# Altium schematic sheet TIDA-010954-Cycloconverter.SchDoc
size 431 x 279 mm; Date: Not shown in title block; ApprovedBy: Not shown in title block; CheckedBy: Not shown in title block; Author: Not shown in title block; CompanyName: Not shown in title block; Engineer: Not shown in title block; Organization: Not shown in title block; Address1: Not shown in title block; Address2: Not shown in title block; Address3: Not shown in title block; Address4: Not shown in title block; DocumentNumber: 2; Revision: Use project parameter SCH_Rev; SheetNumber: 2; SheetTotal: 9; PageSetup: Record=PageOptions¦CenterHorizontal=True¦CenterVertical=True¦PrintScale=1.00¦XCorrection=1.00¦YCorrection=1.00¦PrintKind=0¦BorderSize=5000000¦LeftOffset=0¦BottomOffset=0¦Orientation=2¦PaperLength=1000¦PaperWidth=1000¦Scale=100¦PaperSource=15¦PrintQuality=600¦MediaType=1¦DitherType=10¦PaperKind=Letter¦PrintScaleMode=1
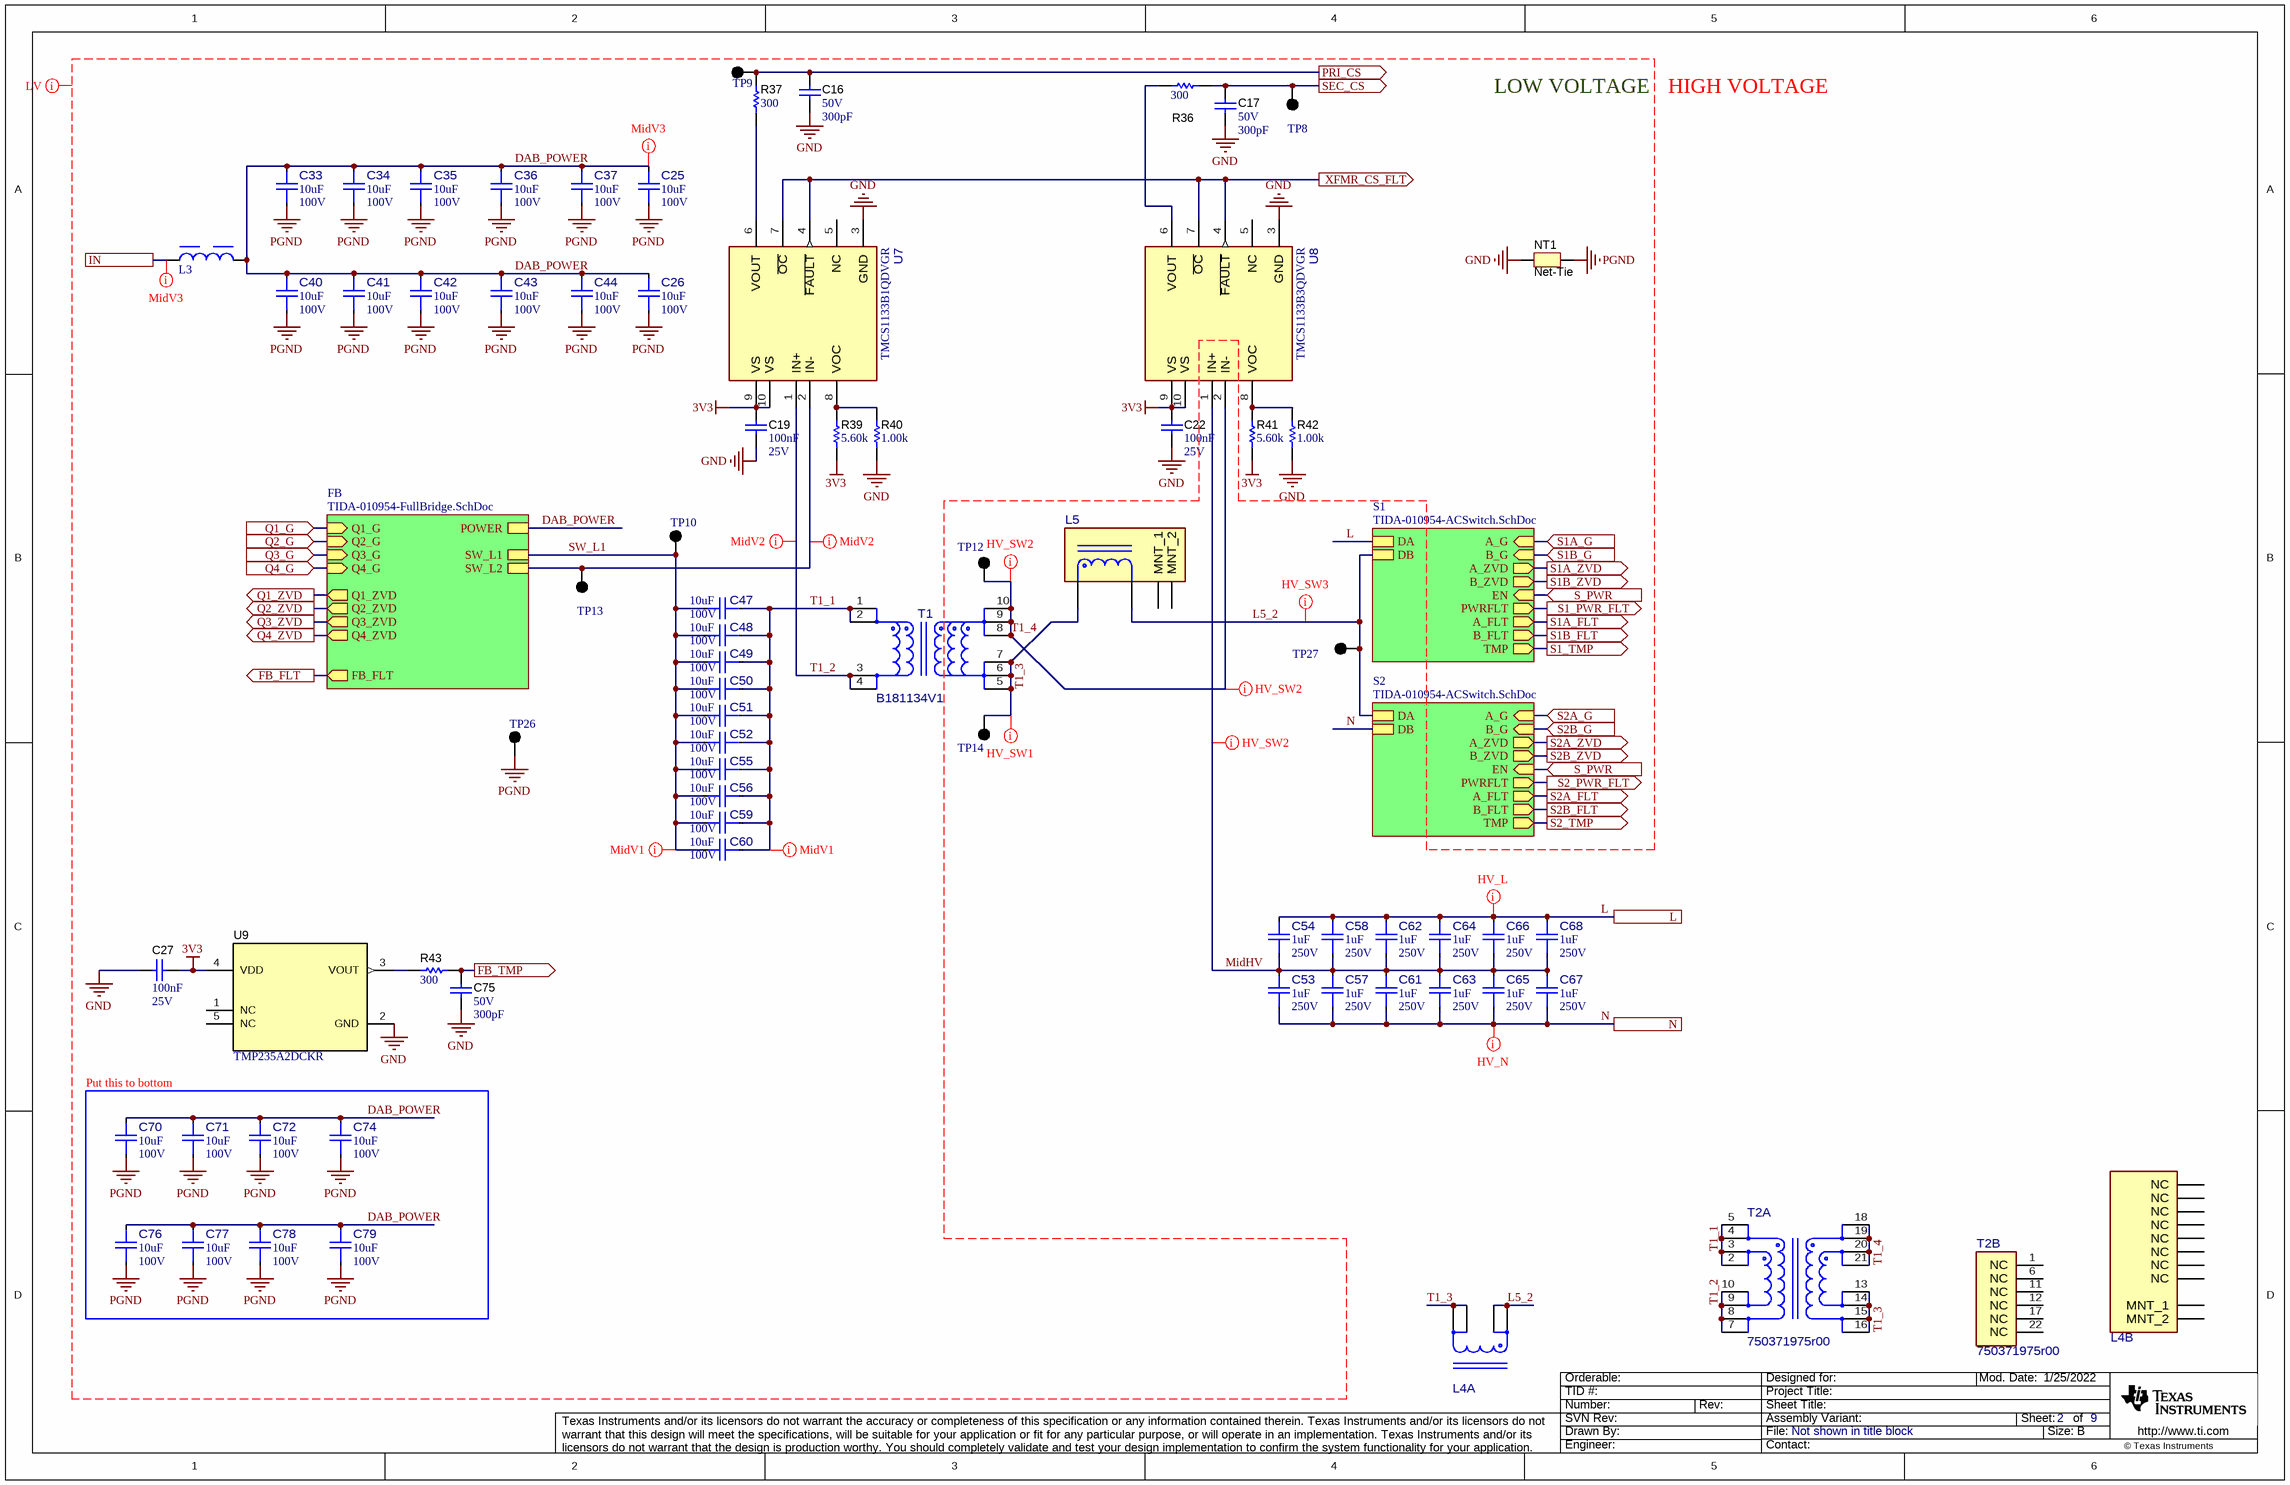
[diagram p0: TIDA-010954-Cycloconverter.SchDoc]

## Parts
C16  VDC_V: 50V  ValueDisplayed: 300pF  [0603]  (hidden comment: GRM1885C1H301JA01D)
C17  VDC_V: 50V  ValueDisplayed: 300pF  [0603]  (hidden comment: GRM1885C1H301JA01D)
C19  Cap_F: 100nF  VDC_V: 25V  [0603]  (hidden comment: CGA3E2X7R1E104K080AA)
C22  Cap_F: 100nF  VDC_V: 25V  [0603]  (hidden comment: CGA3E2X7R1E104K080AA)
C25  ValueDisplayed: 10uF  VDC_V: 100V  [FP-GRM32EC72A106KE05L_1210-MFG]  (hidden comment: GRM32EC72A106KE05L)
C26  ValueDisplayed: 10uF  VDC_V: 100V  [FP-GRM32EC72A106KE05L_1210-MFG]  (hidden comment: GRM32EC72A106KE05L)
C27  Cap_F: 100nF  VDC_V: 25V  [0603]  (hidden comment: CGA3E2X7R1E104K080AA)
C33  ValueDisplayed: 10uF  VDC_V: 100V  [FP-GRM32EC72A106KE05L_1210-MFG]  (hidden comment: GRM32EC72A106KE05L)
C34  ValueDisplayed: 10uF  VDC_V: 100V  [FP-GRM32EC72A106KE05L_1210-MFG]  (hidden comment: GRM32EC72A106KE05L)
C35  ValueDisplayed: 10uF  VDC_V: 100V  [FP-GRM32EC72A106KE05L_1210-MFG]  (hidden comment: GRM32EC72A106KE05L)
C36  ValueDisplayed: 10uF  VDC_V: 100V  [FP-GRM32EC72A106KE05L_1210-MFG]  (hidden comment: GRM32EC72A106KE05L)
C37  ValueDisplayed: 10uF  VDC_V: 100V  [FP-GRM32EC72A106KE05L_1210-MFG]  (hidden comment: GRM32EC72A106KE05L)
C40  ValueDisplayed: 10uF  VDC_V: 100V  [FP-GRM32EC72A106KE05L_1210-MFG]  (hidden comment: GRM32EC72A106KE05L)
C41  ValueDisplayed: 10uF  VDC_V: 100V  [FP-GRM32EC72A106KE05L_1210-MFG]  (hidden comment: GRM32EC72A106KE05L)
C42  ValueDisplayed: 10uF  VDC_V: 100V  [FP-GRM32EC72A106KE05L_1210-MFG]  (hidden comment: GRM32EC72A106KE05L)
C43  ValueDisplayed: 10uF  VDC_V: 100V  [FP-GRM32EC72A106KE05L_1210-MFG]  (hidden comment: GRM32EC72A106KE05L)
C44  ValueDisplayed: 10uF  VDC_V: 100V  [FP-GRM32EC72A106KE05L_1210-MFG]  (hidden comment: GRM32EC72A106KE05L)
C47  ValueDisplayed: 10uF  VDC_V: 100V  [FP-GRM32EC72A106KE05L_1210-MFG]  (hidden comment: GRM32EC72A106KE05L)
C48  ValueDisplayed: 10uF  VDC_V: 100V  [FP-GRM32EC72A106KE05L_1210-MFG]  (hidden comment: GRM32EC72A106KE05L)
C49  ValueDisplayed: 10uF  VDC_V: 100V  [FP-GRM32EC72A106KE05L_1210-MFG]  (hidden comment: GRM32EC72A106KE05L)
C50  ValueDisplayed: 10uF  VDC_V: 100V  [FP-GRM32EC72A106KE05L_1210-MFG]  (hidden comment: GRM32EC72A106KE05L)
C51  ValueDisplayed: 10uF  VDC_V: 100V  [FP-GRM32EC72A106KE05L_1210-MFG]  (hidden comment: GRM32EC72A106KE05L)
C52  ValueDisplayed: 10uF  VDC_V: 100V  [FP-GRM32EC72A106KE05L_1210-MFG]  (hidden comment: GRM32EC72A106KE05L)
C53  ValueDisplayed: 1uF  VDC_V: 250V  [FP-C4532X7T2E105K250KA_1812-MFG]  (hidden comment: C4532X7T2E105K250KA)
C54  ValueDisplayed: 1uF  VDC_V: 250V  [FP-C4532X7T2E105K250KA_1812-MFG]  (hidden comment: C4532X7T2E105K250KA)
C55  ValueDisplayed: 10uF  VDC_V: 100V  [FP-GRM32EC72A106KE05L_1210-MFG]  (hidden comment: GRM32EC72A106KE05L)
C56  ValueDisplayed: 10uF  VDC_V: 100V  [FP-GRM32EC72A106KE05L_1210-MFG]  (hidden comment: GRM32EC72A106KE05L)
C57  ValueDisplayed: 1uF  VDC_V: 250V  [FP-C4532X7T2E105K250KA_1812-MFG]  (hidden comment: C4532X7T2E105K250KA)
C58  ValueDisplayed: 1uF  VDC_V: 250V  [FP-C4532X7T2E105K250KA_1812-MFG]  (hidden comment: C4532X7T2E105K250KA)
C59  ValueDisplayed: 10uF  VDC_V: 100V  [FP-GRM32EC72A106KE05L_1210-MFG]  (hidden comment: GRM32EC72A106KE05L)
C60  ValueDisplayed: 10uF  VDC_V: 100V  [FP-GRM32EC72A106KE05L_1210-MFG]  (hidden comment: GRM32EC72A106KE05L)
C61  ValueDisplayed: 1uF  VDC_V: 250V  [FP-C4532X7T2E105K250KA_1812-MFG]  (hidden comment: C4532X7T2E105K250KA)
C62  ValueDisplayed: 1uF  VDC_V: 250V  [FP-C4532X7T2E105K250KA_1812-MFG]  (hidden comment: C4532X7T2E105K250KA)
C63  ValueDisplayed: 1uF  VDC_V: 250V  [FP-C4532X7T2E105K250KA_1812-MFG]  (hidden comment: C4532X7T2E105K250KA)
C64  ValueDisplayed: 1uF  VDC_V: 250V  [FP-C4532X7T2E105K250KA_1812-MFG]  (hidden comment: C4532X7T2E105K250KA)
C65  ValueDisplayed: 1uF  VDC_V: 250V  [FP-C4532X7T2E105K250KA_1812-MFG]  (hidden comment: C4532X7T2E105K250KA)
C66  ValueDisplayed: 1uF  VDC_V: 250V  [FP-C4532X7T2E105K250KA_1812-MFG]  (hidden comment: C4532X7T2E105K250KA)
C67  ValueDisplayed: 1uF  VDC_V: 250V  [FP-C4532X7T2E105K250KA_1812-MFG]  (hidden comment: C4532X7T2E105K250KA)
C68  ValueDisplayed: 1uF  VDC_V: 250V  [FP-C4532X7T2E105K250KA_1812-MFG]  (hidden comment: C4532X7T2E105K250KA)
C70  ValueDisplayed: 10uF  VDC_V: 100V  [FP-GRM32EC72A106KE05L_1210-MFG]  (hidden comment: GRM32EC72A106KE05L)
C71  ValueDisplayed: 10uF  VDC_V: 100V  [FP-GRM32EC72A106KE05L_1210-MFG]  (hidden comment: GRM32EC72A106KE05L)
C72  ValueDisplayed: 10uF  VDC_V: 100V  [FP-GRM32EC72A106KE05L_1210-MFG]  (hidden comment: GRM32EC72A106KE05L)
C74  ValueDisplayed: 10uF  VDC_V: 100V  [FP-GRM32EC72A106KE05L_1210-MFG]  (hidden comment: GRM32EC72A106KE05L)
C75  VDC_V: 50V  ValueDisplayed: 300pF  [0603]  (hidden comment: GRM1885C1H301JA01D)
C76  ValueDisplayed: 10uF  VDC_V: 100V  [FP-GRM32EC72A106KE05L_1210-MFG]  (hidden comment: GRM32EC72A106KE05L)
C77  ValueDisplayed: 10uF  VDC_V: 100V  [FP-GRM32EC72A106KE05L_1210-MFG]  (hidden comment: GRM32EC72A106KE05L)
C78  ValueDisplayed: 10uF  VDC_V: 100V  [FP-GRM32EC72A106KE05L_1210-MFG]  (hidden comment: GRM32EC72A106KE05L)
C79  ValueDisplayed: 10uF  VDC_V: 100V  [FP-GRM32EC72A106KE05L_1210-MFG]  (hidden comment: GRM32EC72A106KE05L)
L3  7443081030  [WE-HCM_1078_L9.4W6.2H7.8]  (value not drawn)
L4  750371976r00  [FP-750371976r00_XFRMR_22MM0_22MM0-MFG]  (value not drawn)  (parts A,B of 2)
L5  B181125V0  [FP-B181125V0_PTH_IND_41MM45_35MM1-MFG]  (value not drawn)
NT1  Net-Tie  [Net-Tie_50milWide_30milLong]  (net tie, no BOM)
R36  ValueDisplayed: 300  [0603]  (hidden comment: RC0603FR-07300RL)
R37  ValueDisplayed: 300  [0603]  (hidden comment: RC0603FR-07300RL)
R39  ValueDisplayed: 5.60k  [0603]  (hidden comment: RC0603FR-075K6L)
R40  ValueDisplayed: 1.00k  [0603]  (hidden comment: RC0603FR-071KL)
R41  ValueDisplayed: 5.60k  [0603]  (hidden comment: RC0603FR-075K6L)
R42  ValueDisplayed: 1.00k  [0603]  (hidden comment: RC0603FR-071KL)
R43  ValueDisplayed: 300  [0603]  (hidden comment: RC0603FR-07300RL)
T1  B181134V1  [FP-B181134V1_PTH_XFRMR_48MM0_50MM0-MFG]
T2  750371975r00  [FP-750371975r00_PTH_XFRMR_62MM7_62MM8-MFG]  (parts A,B of 2)
TP8  5011  [Keystone5011]  (value not drawn)
TP9  5011  [Keystone5011]  (value not drawn)
TP10  5011  [Keystone5011]  (value not drawn)
TP12  5011  [Keystone5011]  (value not drawn)
TP13  5011  [Keystone5011]  (value not drawn)
TP14  5011  [Keystone5011]  (value not drawn)
TP26  5011  [Keystone5011]  (value not drawn)
TP27  5011  [Keystone5011]  (value not drawn)
U7  TMCS1133B1QDVGR  [DVG0010A-MFG]
U8  TMCS1133B3QDVGR  [DVG0010A-MFG]
U9  PartNumber: TMP235A2DCKR  [DCK0005A_N]  (hidden comment: TMP235DCK)

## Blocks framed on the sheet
Put this to bottom: C70-C72 C74 C76-C79

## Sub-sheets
FB = TIDA-010954-FullBridge.SchDoc: Q1_G (in), Q2_G (in), FB_FLT (out), Q2_ZVD (out), Q1_ZVD (out), Q3_G (in), Q4_G (in), Q4_ZVD (out), Q3_ZVD (out), SW_L1, SW_L2, POWER
S1 = TIDA-010954-ACSwitch.SchDoc: A_G (in), B_G (in), A_ZVD (out), B_ZVD (out), A_FLT (out), B_FLT (out), EN (in), PWRFLT (out), DA, DB, TMP (out)
S2 = TIDA-010954-ACSwitch.SchDoc: A_G (in), B_G (in), A_ZVD (out), B_ZVD (out), A_FLT (out), B_FLT (out), EN (in), PWRFLT (out), DA, DB, TMP (out)

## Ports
FB_FLT (out), FB_TMP (out), IN, L, N, PRI_CS (out), Q1_G (in), Q1_ZVD (out), Q2_G (in), Q2_ZVD (out), Q3_G (in), Q3_ZVD (out), Q4_G (in), Q4_ZVD (out), S1_PWR_FLT (out), S1_TMP (out), S1A_FLT (out), S1A_G (in), S1A_ZVD (out), S1B_FLT (out), S1B_G (in), S1B_ZVD (out), S2_PWR_FLT (out), S2_TMP (out), S2A_FLT (out), S2A_G (in), S2A_ZVD (out), S2B_FLT (out), S2B_G (in), S2B_ZVD (out), S_PWR (in), SEC_CS (out), XFMR_CS_FLT (out)

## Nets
3V3: C19.1 C22.1 C27.1 R39.1 R41.1 U7.9(VS) U7.10(VS) U8.9(VS) U8.10(VS) U9.4(VDD)
GND: C16.2 C17.2 C19.2 C22.2 C27.2 C75.2 NT1.1 R40.1 R42.1 U7.3(GND) U8.3(GND) U9.2(GND)
PGND: C25.1 C26.1 C33.1 C34.1 C35.1 C36.1 C37.1 C40.1 C41.1 C42.1 C43.1 C44.1 C70.1 C71.1 C72.1 C74.1 C76.1 C77.1 C78.1 C79.1 NT1.2 TP26.1
DAB_POWER: C25.2 C26.2 C33.2 C34.2 C35.2 C36.2 C37.2 C40.2 C41.2 C42.2 C43.2 C44.2 C70.2 C71.2 C72.2 C74.2 C76.2 C77.2 C78.2 C79.2 L3.2 ; sheet FB/POWER
FB_FLT: port FB_FLT, sheet FB/FB_FLT
FB_TMP: C75.1 R43.1 ; port FB_TMP
IN: L3.1 ; port IN
L: C54.2 C58.2 C62.2 C64.2 C66.2 C68.2 ; port L, sheet S1/DA
L5_2: L4.1 L4.2 L5.2 TP27.1 ; sheet S1/DB, sheet S2/DA
MidHV: C53.2 C54.1 C57.2 C58.1 C61.2 C62.1 C63.2 C64.1 C65.2 C66.1 C67.2 C68.1 U8.1(IN+)
N: C53.1 C57.1 C61.1 C63.1 C65.1 C67.1 ; port N, sheet S2/DB
PRI_CS: C16.1 R37.2 TP9.1 ; port PRI_CS
Q1_G: port Q1_G, sheet FB/Q1_G
Q1_ZVD: port Q1_ZVD, sheet FB/Q1_ZVD
Q2_G: port Q2_G, sheet FB/Q2_G
Q2_ZVD: port Q2_ZVD, sheet FB/Q2_ZVD
Q3_G: port Q3_G, sheet FB/Q3_G
Q3_ZVD: port Q3_ZVD, sheet FB/Q3_ZVD
Q4_G: port Q4_G, sheet FB/Q4_G
Q4_ZVD: port Q4_ZVD, sheet FB/Q4_ZVD
S1_PWR_FLT: port S1_PWR_FLT, sheet S1/PWRFLT
S1_TMP: port S1_TMP, sheet S1/TMP
S1A_FLT: port S1A_FLT, sheet S1/A_FLT
S1A_G: port S1A_G, sheet S1/A_G
S1A_ZVD: port S1A_ZVD, sheet S1/A_ZVD
S1B_FLT: port S1B_FLT, sheet S1/B_FLT
S1B_G: port S1B_G, sheet S1/B_G
S1B_ZVD: port S1B_ZVD, sheet S1/B_ZVD
S2_PWR_FLT: port S2_PWR_FLT, sheet S2/PWRFLT
S2_TMP: port S2_TMP, sheet S2/TMP
S2A_FLT: port S2A_FLT, sheet S2/A_FLT
S2A_G: port S2A_G, sheet S2/A_G
S2A_ZVD: port S2A_ZVD, sheet S2/A_ZVD
S2B_FLT: port S2B_FLT, sheet S2/B_FLT
S2B_G: port S2B_G, sheet S2/B_G
S2B_ZVD: port S2B_ZVD, sheet S2/B_ZVD
S_PWR: port S_PWR, sheet S1/EN, sheet S2/EN
SEC_CS: C17.1 R36.2 TP8.1 ; port SEC_CS
SW_L1: C47.2 C48.2 C49.2 C50.2 C51.2 C52.2 C55.2 C56.2 C59.2 C60.2 TP10.1 ; sheet FB/SW_L1
T1_1: C47.1 C48.1 C49.1 C50.1 C51.1 C52.1 C55.1 C56.1 C59.1 C60.1 T1.1 T1.2 T2.2 T2.3 T2.4 T2.5
T1_2: T1.3 T1.4 T2.7 T2.8 T2.9 T2.10 U7.1(IN+)
T1_3: L4.7 L4.8 L5.1 T1.5 T1.6 T1.7 T2.13 T2.14 T2.15 T2.16 TP14.1
T1_4: T1.8 T1.9 T1.10 T2.18 T2.19 T2.20 T2.21 TP12.1 U8.2(IN-)
XFMR_CS_FLT: U7.4(~{FAULT}) U7.7(~{OC}) U8.4(~{FAULT}) U8.7(~{OC}) ; port XFMR_CS_FLT
NetR36_1: R36.1 U8.6(VOUT)
NetR37_1: R37.1 U7.6(VOUT)
NetR39_2: R39.2 R40.2 U7.8(VOC)
NetR41_2: R41.2 R42.2 U8.8(VOC)
NetR43_2: R43.2 U9.3(VOUT)
NetTP13_1: TP13.1 U7.2(IN-) ; sheet FB/SW_L2

Not connected (* = marked no-connect by the designer): L4 3(NC) 4(NC) 5(NC) 6(NC) 9(NC) 10(NC) 11(NC) 12(NC) 13(MNT_1) 14(MNT_2); L5 3(MNT_1) 4(MNT_2); T2 1(NC) 6(NC) 11(NC) 12(NC) 17(NC) 22(NC); U7 5(NC); U8 5(NC); U9 1(NC) 5(NC)

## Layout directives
net class HV_SW1: T1_3
net class HV_SW2: MidHV, T1_4
net class HV_L: L
net class HV_SW3: L5_2
net class HV_N: N
net class MidV3: DAB_POWER, IN
net class LV: 3V3, DAB_POWER, GND, L, L5_2, MidHV, N, PGND, SW_L1, T1_1, T1_2, T1_3, T1_4
net class MidV2: NetTP13_1, T1_2
net class MidV1: SW_L1, T1_1

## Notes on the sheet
- LOW VOLTAGE
- HIGH VOLTAGE

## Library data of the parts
C16 C17 C75 = CMP-0007206-4: CAP, CERM, 300 pF, 50 V, +/- 5%, C0G/NP0, 0603; Manufacturer: MuRata; TaMin_C: -55°C; Polarized: N; SizeAreaWB_mm2: 4.68; Value1: Unknown; U/M: EA; Value: 300pF; TaMax_C: 125°C; SizeZ_mm: 1; SizeX_mm: 1.6; SizeY_mm: 0.8; SizeArea_mm2: 1.28; AEC Category: Q200
C19 C22 C27 = CMP-0007077-5: CAP, CERM, 0.1 uF, 25 V, +/- 10%, X7R, AEC-Q200 Grade 1, 0603; Manufacturer: TDK; TaMin_C: -55°C; Polarized: N; SizeAreaWB_mm2: 4.68; Value1: Unknown; U/M: EA; Value: 0.1uF; TaMax_C: 125°C; SizeZ_mm: 1; SizeX_mm: 1.6; SizeY_mm: 0.8; SizeArea_mm2: 1.28; AEC Qualified: Y; AEC Category: Q200
C25 C26 C33-C37 C40-C44 C47-C52 C55 C56 C59 C60 C70-C72 C74 C76-C79 = CMP-0087970-1: 10µF ±10% 100V Ceramic Capacitor X7S 1210 (3225 Metric); Manufacturer: Murata; Symbol Name: SYM-GRM32EC72A106KE05L; Tolerance_%: 0.1; AEC Qualified: No; TempCo: 22%; SizeZ_mm: 2.7mm
C53 C54 C57 C58 C61-C68 = CMP-0091547-1: Multilayer Ceramic Capacitors 1uF ±10% 250V X7T SMD 1812; Manufacturer: TDK; Cap_F: 1µF; Tolerance_%: 0.1%; TempCo: +22/-33%; Value: 1µF; SizeZ_mm: 2.8mm; AEC Qualified: No
L3 = CMP-0098580-1: WE-HCM SMT High Current Flat Wire Inductor, size 1078, 0.14uH, 38A, 0.29mOhm; Manufacturer: Wurth Elektronik; Material: MnZn; Case/Size Code: 1078; Inductance: 0.3uH; Saturation Current: 34.6A; Self Resonant Frequency: 33MHz
L4 = CMP-0123014-1: Inductor, 3 uH, 3mOhm; Manufacturer: Wurth Electronics; AEC Qualified: No; DCR_ohm: 3m; Ind_H: 3µH; SizeZ_mm: 17.27mm; Value: 3uH; Test Frequency: 10kHz; Tolerance_%: 10%
L5 = CMP-0123108-1: Inductor 5uH; Manufacturer: Bourns; AEC Qualified: No; DCR_ohm: 3.6m; Ind_H: 5µH; Isat: 20A; SizeZ_mm: 16.75mm; Test Frequency: 100kHz; Tolerance_%: 10%
NT1 = CMP-0078142-6: Single point connection between nets.
R36 R37 R43 = CMP-0023013-5: RES, 300, 1%, 0.1 W, 0603; Manufacturer: Yageo; Power_W: 100mW; TempCo: 100 ppm/C; Value_Code: 300R; Value: 300; SizeX_mm: 1.6; SizeY_mm: 0.8; SizeZ_mm: 1; Value2: 0.1W; SizeArea_mm2: 1.28; AEC Qualified: N; VDC_V: 75V; AEC Category: Q200; SizeAreaWB_mm2: 4.68
R39 R41 = CMP-0023203-5: RES, 5.60 k, 1%, 0.1 W, 0603; Manufacturer: Yageo; Power_W: 100mW; TempCo: 100 ppm/C; Value_Code: 5k60; Value: 5.60k; Res_ohm: 5.6k; SizeX_mm: 1.6; SizeY_mm: 0.8; SizeZ_mm: 1; Value2: 0.1W; SizeArea_mm2: 1.28; AEC Qualified: N; VDC_V: 75V; AEC Category: Q200; SizeAreaWB_mm2: 4.68
R40 R42 = CMP-0022895-5: RES, 1.00 k, 1%, 0.1 W, 0603; Manufacturer: Yageo; Power_W: 100mW; TempCo: 100 ppm/C; Value_Code: 1k00; Value: 1.00k; EIA_Code: E96; Res_ohm: 1k; SizeX_mm: 1.6; SizeY_mm: 0.8; SizeZ_mm: 1; Value2: 0.1W; SizeArea_mm2: 1.28; AEC Qualified: N; VDC_V: 75V; AEC Category: Q200; SizeAreaWB_mm2: 4.68
T1 = CMP-0123122-1: Transformer; Manufacturer: Bourns; DCR_ohm: 1.14m; Ind_H: 7.6µH; Ns1toNp: 1:3.5; Rsec1_ohm: 14m; SizeZ_mm: 32mm; AEC Qualified: No; Voltage_Isolation_Vrms: 3kV
T2 = CMP-0122999-1: TRANSFORMER; Manufacturer: Wurth Electronics; DCR_ohm: 4m; Ind_H: 10µH; Ns1toNp: 1:3.5; Rsec1_ohm: 47m; SizeZ_mm: 46.3mm; AEC Qualified: No; Voltage_Isolation_Vrms: 3.5kV
TP8-TP10 TP12-TP14 TP26 TP27 = CMP-0055148-2: Test Point, Multipurpose, Black, TH; Manufacturer: Keystone Electronics; CNHeader: FALSE; ContactFinish: Silver; Green_REACh: Passed; Green_Lifecycle: Active; CT: TRUE
U7 = CMP-0097984-1: Manufacturer: Texas Instruments; Standoff Height: 0.1mm; SizeZ_mm: 2.65mm
U8 = CMP-0097986-1: Manufacturer: Texas Instruments; SizeZ_mm: 2.65mm; Standoff Height: 0.1mm
U9 = CMP-0013250-3: TMP235DCK, DCK0005A (SOT-5); Manufacturer: Texas Instruments; SizeX_mm: 2.1; SizeY_mm: 2.0; CompType: IC; SizeZ_mm: 1.1; SizeArea_mm2: 4.2; SizeAreaWB_mm2: 9.3; AEC Category: Q200; AEC Qualified: N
